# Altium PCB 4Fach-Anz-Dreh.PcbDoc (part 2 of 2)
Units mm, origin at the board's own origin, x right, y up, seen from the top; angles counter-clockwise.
Board outline 160 x 100 mm, 2 copper layers (Top Layer, Bottom Layer), stack 1.601 mm thick; 204 components, 197 nets, 945 pads, 254 vias.
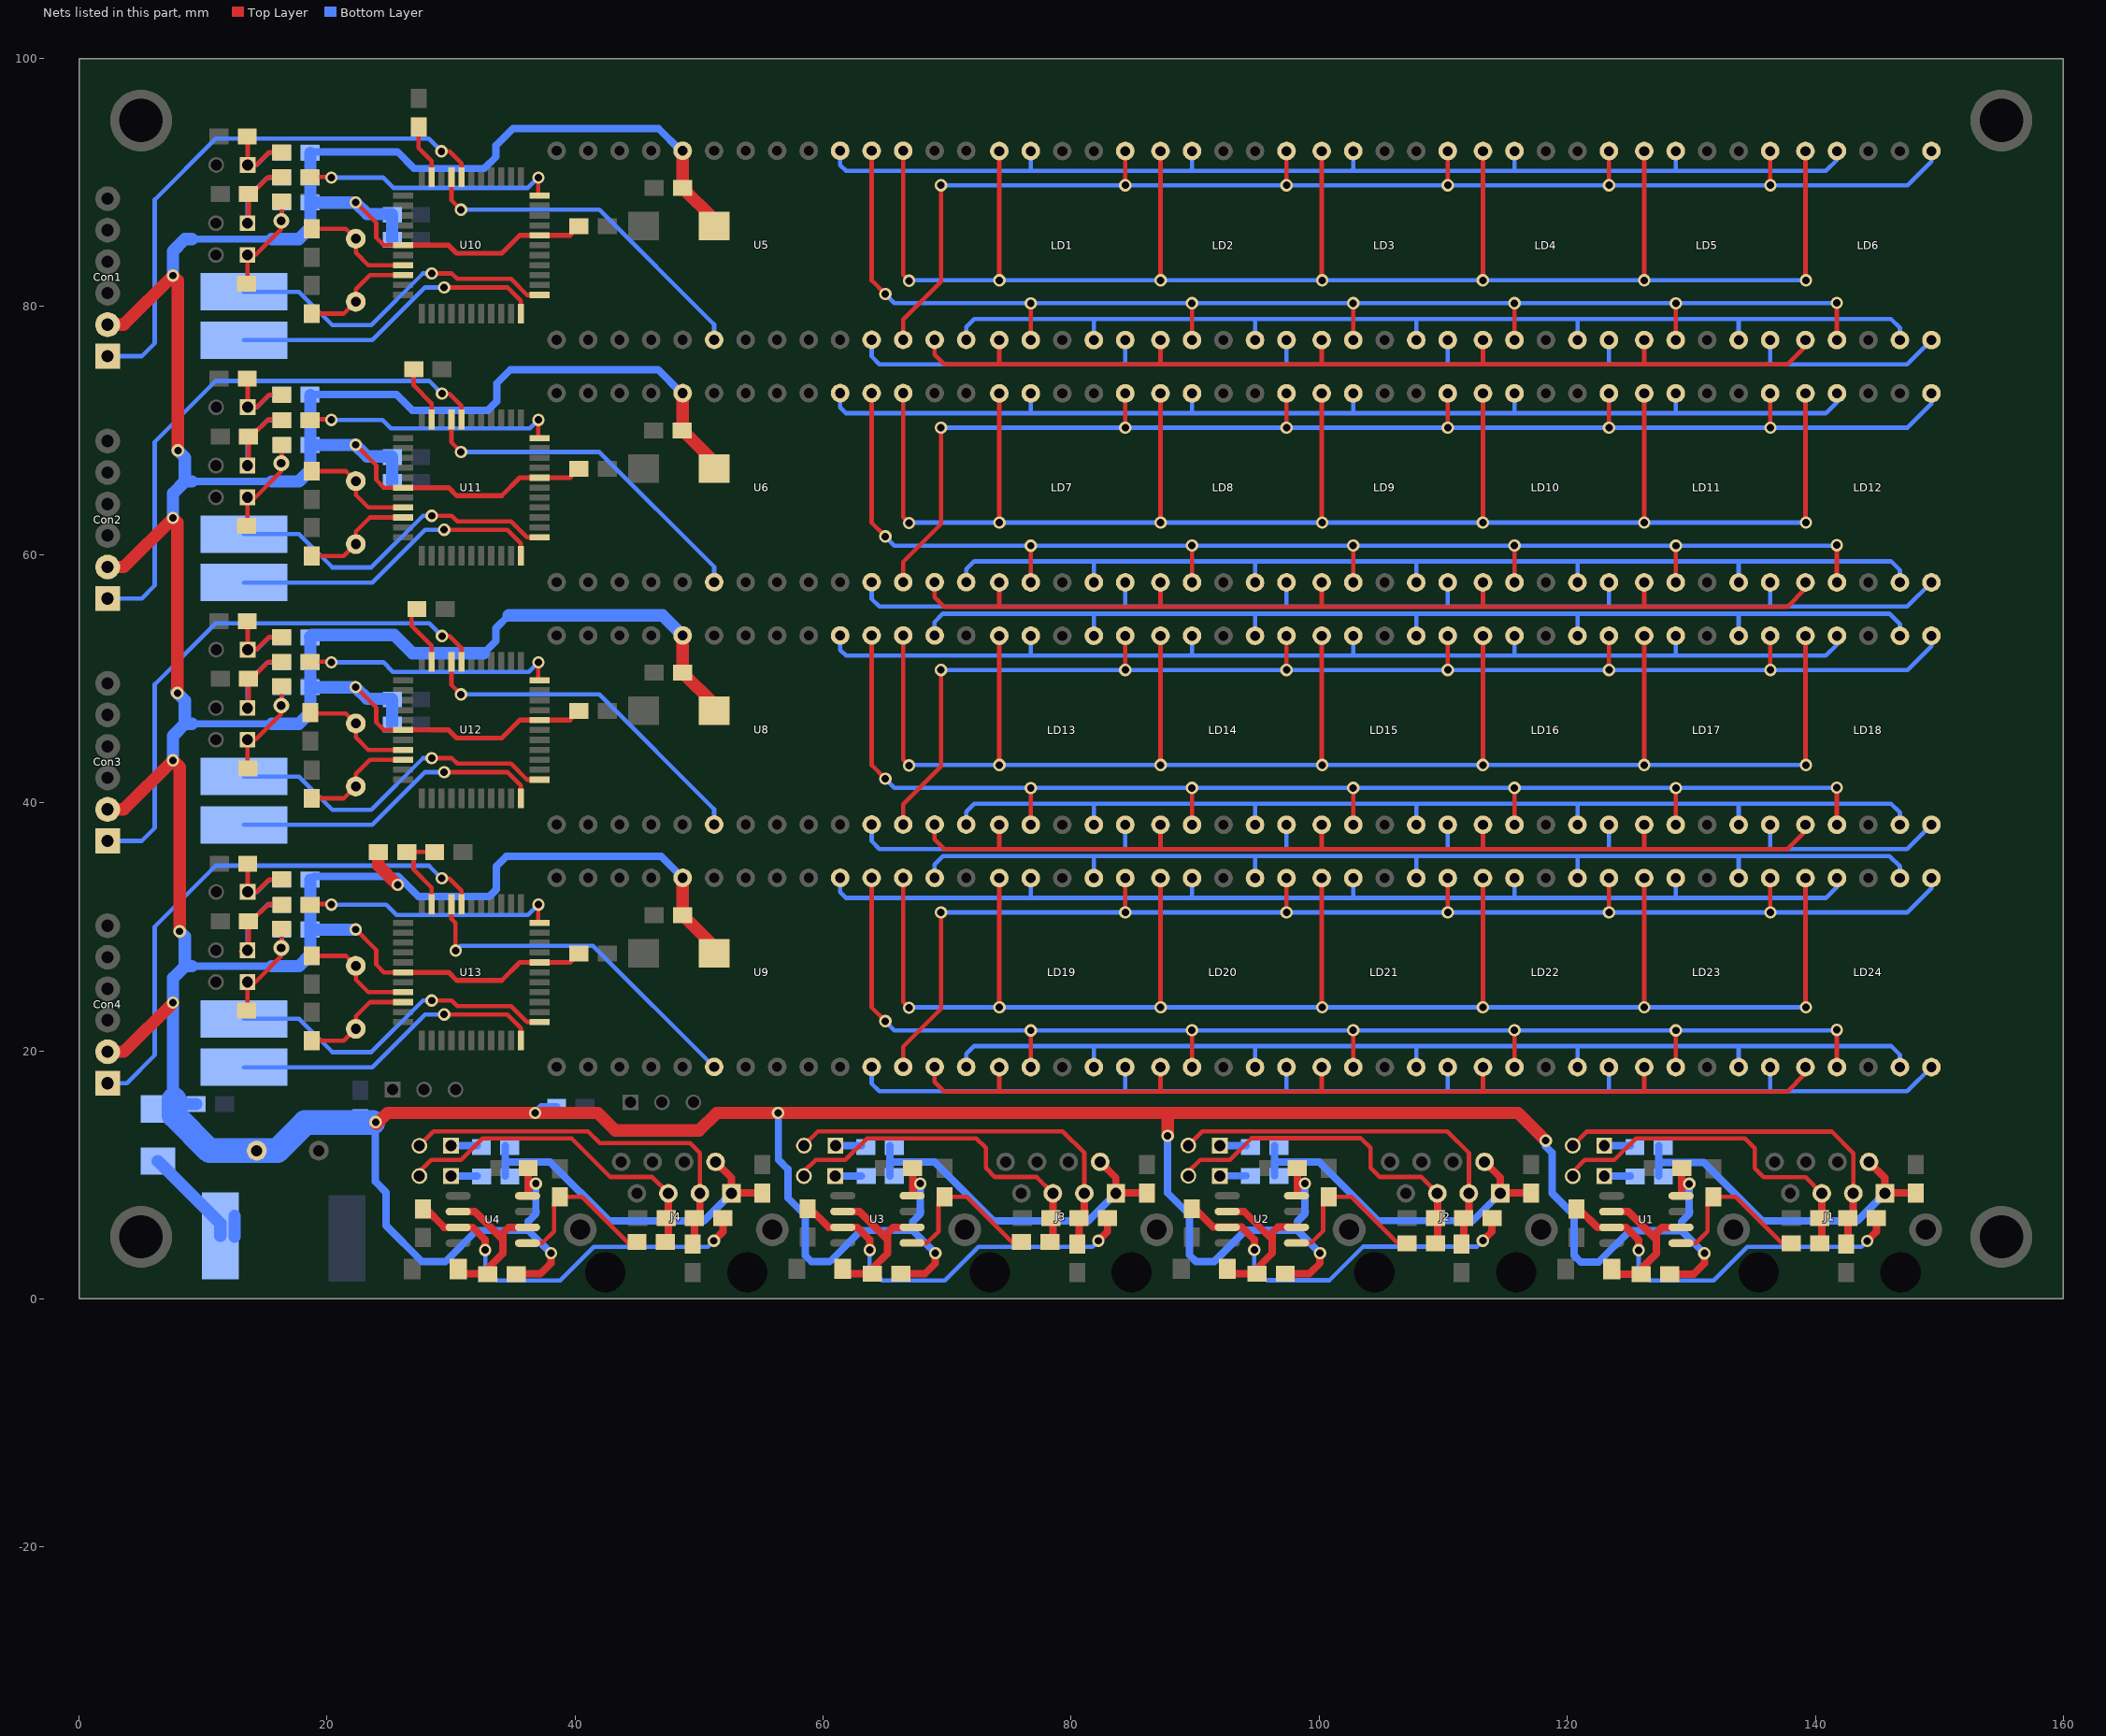
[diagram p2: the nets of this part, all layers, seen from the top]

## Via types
v1: diameter 1, hole 0.6, Top Layer to Bottom Layer, 249 vias
v2: diameter 1.27, hole 0.711, Top Layer to Bottom Layer, 5 vias

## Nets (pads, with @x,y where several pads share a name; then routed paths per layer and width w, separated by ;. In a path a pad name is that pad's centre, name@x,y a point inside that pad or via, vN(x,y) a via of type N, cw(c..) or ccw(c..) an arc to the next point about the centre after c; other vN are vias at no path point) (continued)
LED-A-3: LD13.7 LD14.7 LD15.7 LD16.7 LD17.7 LD18.7 U8.27 | length 89.4
  Bottom Layer w0.35: U8.27@68.99,53.48 68.99,54.56 69.67,55.24 81.82,55.24 ; LD13.7@81.82,53.46 81.82,55.24 ; LD14.7@94.82,53.46 94.82,55.24 ; LD15.7@107.82,53.46 107.82,55.24 ; LD16.7@120.82,53.46 120.82,55.24 ; LD17.7@133.82,53.46 133.82,55.24 ; LD18.7@146.82,53.46 146.82,54.4 145.98,55.24 133.82,55.24 ; 81.82,55.24 94.82,55.24 ; 94.82,55.24 107.82,55.24 ; 107.82,55.24 120.82,55.24 ; 120.82,55.24 133.82,55.24
LED-A-4: LD19.7 LD20.7 LD21.7 LD22.7 LD23.7 LD24.7 U9.27 | length 89.4
  Bottom Layer w0.35: U9.27@68.99,33.94 68.99,35.02 69.67,35.7 81.82,35.7 ; LD19.7@81.82,33.92 81.82,35.7 ; LD20.7@94.82,33.92 94.82,35.7 ; LD21.7@107.82,33.92 107.82,35.7 ; LD22.7@120.82,33.92 120.82,35.7 ; LD23.7@133.82,33.92 133.82,35.7 ; LD24.7@146.82,33.92 146.82,34.86 145.98,35.7 133.82,35.7 ; 81.82,35.7 94.82,35.7 ; 94.82,35.7 107.82,35.7 ; 107.82,35.7 120.82,35.7 ; 120.82,35.7 133.82,35.7
LED-B-1: LD1.6 LD2.6 LD3.6 LD4.6 LD5.6 LD6.6 U5.3 | length 109
  Top Layer w0.35: U5.3@66.45,77.32 66.45,78.96 69.5,82.01 v1(69.5,89.78) ; v1(84.36,89.78) LD1.6@84.36,92.54 ; v1(97.36,89.78) LD2.6@97.36,92.54 ; v1(110.36,89.78) LD3.6@110.36,92.54 ; v1(123.36,89.78) LD4.6@123.36,92.54 ; LD5.6@136.36,92.54 136.36,89.79 v1(136.37,89.78)
  Bottom Layer w0.35: v1(69.5,89.78) v1(84.36,89.78) ; LD6.6@149.36,92.54 149.36,91.7 147.44,89.78 v1(136.37,89.78) v1@123.37,89.78 ; v1(84.36,89.78) v1@84.37,89.78 ; v1(84.36,89.78) v1@84.37,89.78 ; v1@84.37,89.78 v1(97.36,89.78) v1(110.36,89.78) v1(123.36,89.78) ; v1(123.36,89.78) v1@123.37,89.78 ; v1(123.36,89.78) v1@123.37,89.78
LED-B-2: LD7.6 LD8.6 LD9.6 LD10.6 LD11.6 LD12.6 U6.3 | length 109
  Top Layer w0.35: U6.3@66.45,57.78 66.45,59.42 69.5,62.47 v1(69.5,70.24) ; v1(84.36,70.24) LD7.6@84.36,73 ; v1(97.36,70.24) LD8.6@97.36,73 ; v1(110.36,70.24) LD9.6@110.36,73 ; v1(123.36,70.24) LD10.6@123.36,73 ; LD11.6@136.36,73 136.36,70.25 v1(136.37,70.24)
  Bottom Layer w0.35: v1(69.5,70.24) v1(84.36,70.24) ; v2(149.36,73) 149.36,72.16 147.44,70.24 v1(136.37,70.24) v1@123.37,70.24 ; v1(84.36,70.24) v1@84.37,70.24 ; v1(84.36,70.24) v1@84.37,70.24 ; v1@84.37,70.24 v1(97.36,70.24) v1(110.36,70.24) v1(123.36,70.24) ; v1(123.36,70.24) v1@123.37,70.24 ; v1(123.36,70.24) v1@123.37,70.24
LED-B-3: LD13.6 LD14.6 LD15.6 LD16.6 LD17.6 LD18.6 U8.3 | length 109
  Top Layer w0.35: U8.3@66.45,38.24 66.45,39.88 69.5,42.93 v1(69.5,50.7) ; v1(84.36,50.7) LD13.6@84.36,53.46 ; v1(97.36,50.7) LD14.6@97.36,53.46 ; v1(110.36,50.7) LD15.6@110.36,53.46 ; v1(123.36,50.7) LD16.6@123.36,53.46 ; LD17.6@136.36,53.46 136.36,50.71 v1(136.37,50.7)
  Bottom Layer w0.35: v1(69.5,50.7) v1(84.36,50.7) ; LD18.6@149.36,53.46 149.36,52.62 147.44,50.7 v1(136.37,50.7) v1@123.37,50.7 ; v1(84.36,50.7) v1@84.37,50.7 ; v1(84.36,50.7) v1@84.37,50.7 ; v1@84.37,50.7 v1(97.36,50.7) v1(110.36,50.7) v1(123.36,50.7) ; v1(123.36,50.7) v1@123.37,50.7 ; v1(123.36,50.7) v1@123.37,50.7
LED-B-4: LD19.6 LD20.6 LD21.6 LD22.6 LD23.6 LD24.6 U9.3 | length 109
  Top Layer w0.35: U9.3@66.45,18.7 66.45,20.34 69.5,23.39 v1(69.5,31.16) ; v1(84.36,31.16) LD19.6@84.36,33.92 ; v1(97.36,31.16) LD20.6@97.36,33.92 ; v1(110.36,31.16) LD21.6@110.36,33.92 ; v1(123.36,31.16) LD22.6@123.36,33.92 ; LD23.6@136.36,33.92 136.36,31.17 v1(136.37,31.16)
  Bottom Layer w0.35: v1(69.5,31.16) v1(84.36,31.16) ; LD24.6@149.36,33.92 149.36,33.08 147.44,31.16 v1(136.37,31.16) v1@123.37,31.16 ; v1(84.36,31.16) v1@84.37,31.16 ; v1(84.36,31.16) v1@84.37,31.16 ; v1@84.37,31.16 v1(97.36,31.16) v1(110.36,31.16) v1(123.36,31.16) ; v1(123.36,31.16) v1@123.37,31.16 ; v1(123.36,31.16) v1@123.37,31.16
LED-C-1: LD1.4 LD2.4 LD3.4 LD4.4 LD5.4 LD6.4 U5.1 | length 86.3
  Bottom Layer w0.35: U5.1@71.53,77.32 71.53,78.36 72.17,79 81.8,79 ; LD1.4@81.82,77.3 81.82,78.98 81.8,79 ; LD2.4@94.82,77.3 94.82,78.95 94.87,79 ; LD3.4@107.82,77.3 107.82,78.97 107.85,79 ; LD4.4@120.82,77.3 120.82,78.98 ; LD5.4@133.82,77.3 133.82,78.9 ; LD6.4@146.82,77.3 146.82,78.28 146.1,79 107.85,79 ; 81.8,79 94.87,79 ; 94.87,79 107.85,79
LED-C-2: LD7.4 LD8.4 LD9.4 LD10.4 LD11.4 LD12.4 U6.1 | length 86.3
  Bottom Layer w0.35: U6.1@71.53,57.78 71.53,58.82 72.17,59.46 81.8,59.46 ; LD7.4@81.82,57.76 81.82,59.44 81.8,59.46 ; LD8.4@94.82,57.76 94.82,59.41 94.87,59.46 ; LD9.4@107.82,57.76 107.82,59.43 107.85,59.46 ; LD10.4@120.82,57.76 120.82,59.44 ; LD11.4@133.82,57.76 133.82,59.36 ; LD12.4@146.82,57.76 146.82,58.74 146.1,59.46 107.85,59.46 ; 81.8,59.46 94.87,59.46 ; 94.87,59.46 107.85,59.46
LED-C-3: LD13.4 LD14.4 LD15.4 LD16.4 LD17.4 LD18.4 U8.1 | length 86.3
  Bottom Layer w0.35: U8.1@71.53,38.24 71.53,39.28 72.17,39.92 81.8,39.92 ; LD13.4@81.82,38.22 81.82,39.9 81.8,39.92 ; LD14.4@94.82,38.22 94.82,39.87 94.87,39.92 ; LD15.4@107.82,38.22 107.82,39.89 107.85,39.92 ; LD16.4@120.82,38.22 120.82,39.9 ; LD17.4@133.82,38.22 133.82,39.82 ; LD18.4@146.82,38.22 146.82,39.2 146.1,39.92 107.85,39.92 ; 81.8,39.92 94.87,39.92 ; 94.87,39.92 107.85,39.92
LED-C-4: LD19.4 LD20.4 LD21.4 LD22.4 LD23.4 LD24.4 U9.1 | length 86.3
  Bottom Layer w0.35: U9.1@71.53,18.7 71.53,19.74 72.17,20.38 81.8,20.38 ; LD19.4@81.82,18.68 81.82,20.36 81.8,20.38 ; LD20.4@94.82,18.68 94.82,20.33 94.87,20.38 ; LD21.4@107.82,18.68 107.82,20.35 107.85,20.38 ; LD22.4@120.82,18.68 120.82,20.36 ; LD23.4@133.82,18.68 133.82,20.28 ; LD24.4@146.82,18.68 146.82,19.66 146.1,20.38 107.85,20.38 ; 81.8,20.38 94.87,20.38 ; 94.87,20.38 107.85,20.38
LED-D-1: LD1.2 LD2.2 LD3.2 LD4.2 LD5.2 LD6.2 U5.25 | length 106.9
  Top Layer w0.35: U5.25@63.91,92.56 63.91,82.11 v1(65.01,81.01) ; LD1.2@76.74,77.3 v1(76.74,80.26) ; LD2.2@89.74,77.3 v1(89.74,80.27) ; LD3.2@102.74,77.3 v1(102.74,80.27) ; LD4.2@115.74,77.3 v1(115.74,80.27) ; LD5.2@128.74,77.3 128.74,80.25 v1(128.75,80.26) ; v1(141.73,80.3) 141.73,77.31 LD6.2@141.74,77.3
  Bottom Layer w0.35: v1(65.01,81.01) 65.75,80.27 v1@76.74,80.27 ; v1(76.74,80.26) v1@76.74,80.27 ; v1(128.75,80.26) v1@128.75,80.27 ; v1(141.73,80.3) 141.7,80.27 v1@128.75,80.27 ; v1@76.74,80.27 v1(89.74,80.27) v1(102.74,80.27) v1(115.74,80.27) v1@128.75,80.27
LED-D-2: LD7.2 LD8.2 LD9.2 LD10.2 LD11.2 LD12.2 U6.25 | length 106.9
  Top Layer w0.35: U6.25@63.91,73.02 63.91,62.57 v1(65.01,61.47) ; LD7.2@76.74,57.76 v1(76.74,60.72) ; LD8.2@89.74,57.76 v1(89.74,60.73) ; LD9.2@102.74,57.76 v1(102.74,60.73) ; LD10.2@115.74,57.76 v1(115.74,60.73) ; LD11.2@128.74,57.76 128.74,60.71 v1(128.75,60.72) ; v1(141.73,60.76) 141.73,57.77 LD12.2@141.74,57.76
  Bottom Layer w0.35: v1(65.01,61.47) 65.75,60.73 v1@76.74,60.73 ; v1(76.74,60.72) v1@76.74,60.73 ; v1(128.75,60.72) v1@128.75,60.73 ; v1(141.73,60.76) 141.7,60.73 v1@128.75,60.73 ; v1@76.74,60.73 v1(89.74,60.73) v1(102.74,60.73) v1(115.74,60.73) v1@128.75,60.73
LED-D-3: LD13.2 LD14.2 LD15.2 LD16.2 LD17.2 LD18.2 U8.25 | length 106.9
  Top Layer w0.35: U8.25@63.91,53.48 63.91,43.03 v1(65.01,41.93) ; LD13.2@76.74,38.22 v1(76.74,41.18) ; LD14.2@89.74,38.22 v1(89.74,41.19) ; LD15.2@102.74,38.22 v1(102.74,41.19) ; LD16.2@115.74,38.22 v1(115.74,41.19) ; LD17.2@128.74,38.22 128.74,41.17 v1(128.75,41.18) ; v1(141.73,41.22) 141.73,38.23 LD18.2@141.74,38.22
  Bottom Layer w0.35: v1(65.01,41.93) 65.75,41.19 v1@76.74,41.19 ; v1(76.74,41.18) v1@76.74,41.19 ; v1(128.75,41.18) v1@128.75,41.19 ; v1(141.73,41.22) 141.7,41.19 v1@128.75,41.19 ; v1@76.74,41.19 v1(89.74,41.19) v1(102.74,41.19) v1(115.74,41.19) v1@128.75,41.19
LED-D-4: LD19.2 LD20.2 LD21.2 LD22.2 LD23.2 LD24.2 U9.25 | length 106.9
  Top Layer w0.35: U9.25@63.91,33.94 63.91,23.49 v1(65.01,22.39) ; LD19.2@76.74,18.68 v1(76.74,21.64) ; LD20.2@89.74,18.68 v1(89.74,21.65) ; LD21.2@102.74,18.68 v1(102.74,21.65) ; LD22.2@115.74,18.68 v1(115.74,21.65) ; LD23.2@128.74,18.68 128.74,21.63 v1(128.75,21.64) ; v1(141.73,21.68) 141.73,18.69 LD24.2@141.74,18.68
  Bottom Layer w0.35: v1(65.01,22.39) 65.75,21.65 v1@76.74,21.65 ; v1(76.74,21.64) v1@76.74,21.65 ; v1(128.75,21.64) v1@128.75,21.65 ; v1(141.73,21.68) 141.7,21.65 v1@128.75,21.65 ; v1@76.74,21.65 v1(89.74,21.65) v1(102.74,21.65) v1(115.74,21.65) v1@128.75,21.65
LED-DP-1: LD1.5 LD2.5 LD3.5 LD4.5 LD5.5 LD6.5 U5.4 | length 97.6
  Bottom Layer w0.35: U5.4@63.91,77.32 63.91,75.97 64.53,75.35 84.38,75.35 ; LD1.5@84.36,77.3 84.36,75.37 84.38,75.35 ; LD2.5@97.36,77.3 97.36,75.37 97.38,75.35 ; 110.36,75.4 LD3.5@110.36,77.3 ; LD4.5@123.36,77.3 123.36,75.35 ; LD5.5@136.36,77.3 136.36,75.42 136.43,75.35 ; LD6.5@149.36,77.3 147.41,75.35 136.43,75.35 ; 84.38,75.35 97.38,75.35 ; 97.38,75.35 123.36,75.35 ; 123.36,75.35 136.43,75.35
LED-DP-2: LD7.5 LD8.5 LD9.5 LD10.5 LD11.5 LD12.5 U6.4 | length 97.6
  Bottom Layer w0.35: U6.4@63.91,57.78 63.91,56.43 64.53,55.81 84.38,55.81 ; LD7.5@84.36,57.76 84.36,55.83 84.38,55.81 ; LD8.5@97.36,57.76 97.36,55.83 97.38,55.81 ; 110.36,55.86 LD9.5@110.36,57.76 ; LD10.5@123.36,57.76 123.36,55.81 ; LD11.5@136.36,57.76 136.36,55.88 136.43,55.81 ; LD12.5@149.36,57.76 147.41,55.81 136.43,55.81 ; 84.38,55.81 97.38,55.81 ; 97.38,55.81 123.36,55.81 ; 123.36,55.81 136.43,55.81
LED-DP-3: LD13.5 LD14.5 LD15.5 LD16.5 LD17.5 LD18.5 U8.4 | length 97.6
  Bottom Layer w0.35: U8.4@63.91,38.24 63.91,36.89 64.53,36.27 84.38,36.27 ; LD13.5@84.36,38.22 84.36,36.29 84.38,36.27 ; LD14.5@97.36,38.22 97.36,36.29 97.38,36.27 ; 110.36,36.32 LD15.5@110.36,38.22 ; LD16.5@123.36,38.22 123.36,36.27 ; LD17.5@136.36,38.22 136.36,36.34 136.43,36.27 ; LD18.5@149.36,38.22 147.41,36.27 136.43,36.27 ; 84.38,36.27 97.38,36.27 ; 97.38,36.27 123.36,36.27 ; 123.36,36.27 136.43,36.27
LED-DP-4: LD19.5 LD20.5 LD21.5 LD22.5 LD23.5 LD24.5 U9.4 | length 97.6
  Bottom Layer w0.35: U9.4@63.91,18.7 63.91,17.35 64.53,16.73 84.38,16.73 ; LD19.5@84.36,18.68 84.36,16.75 84.38,16.73 ; LD20.5@97.36,18.68 97.36,16.75 97.38,16.73 ; 110.36,16.78 LD21.5@110.36,18.68 ; LD22.5@123.36,18.68 123.36,16.73 ; LD23.5@136.36,18.68 136.36,16.8 136.43,16.73 ; LD24.5@149.36,18.68 147.41,16.73 136.43,16.73 ; 84.38,16.73 97.38,16.73 ; 97.38,16.73 123.36,16.73 ; 123.36,16.73 136.43,16.73
LED-E-1: LD1.1 LD2.1 LD3.1 LD4.1 LD5.1 LD6.1 U5.2 | length 82.6
  Top Layer w0.35: U5.2@68.99,77.32 68.99,76.12 69.78,75.33 100.19,75.33 ; 74.2,75.41 LD1.1@74.2,77.3 ; 87.2,75.39 LD2.1@87.2,77.3 ; LD3.1@100.2,77.3 100.2,75.34 100.19,75.33 ; LD4.1@113.2,77.3 113.2,75.34 113.19,75.33 ; LD5.1@126.2,77.3 126.2,75.34 126.19,75.33 ; LD6.1@139.2,77.3 139.2,76.78 137.75,75.33 126.19,75.33 ; 100.19,75.33 113.19,75.33 ; 113.19,75.33 126.19,75.33
LED-E-2: LD7.1 LD8.1 LD9.1 LD10.1 LD11.1 LD12.1 U6.2 | length 82.6
  Top Layer w0.35: U6.2@68.99,57.78 68.99,56.58 69.78,55.79 100.19,55.79 ; 74.2,55.87 LD7.1@74.2,57.76 ; 87.2,55.85 LD8.1@87.2,57.76 ; LD9.1@100.2,57.76 100.2,55.8 100.19,55.79 ; LD10.1@113.2,57.76 113.2,55.8 113.19,55.79 ; LD11.1@126.2,57.76 126.2,55.8 126.19,55.79 ; LD12.1@139.2,57.76 139.2,57.24 137.75,55.79 126.19,55.79 ; 100.19,55.79 113.19,55.79 ; 113.19,55.79 126.19,55.79
LED-E-3: LD13.1 LD14.1 LD15.1 LD16.1 LD17.1 LD18.1 U8.2 | length 82.6
  Top Layer w0.35: U8.2@68.99,38.24 68.99,37.04 69.78,36.25 100.19,36.25 ; 74.2,36.33 LD13.1@74.2,38.22 ; 87.2,36.31 LD14.1@87.2,38.22 ; LD15.1@100.2,38.22 100.2,36.26 100.19,36.25 ; LD16.1@113.2,38.22 113.2,36.26 113.19,36.25 ; LD17.1@126.2,38.22 126.2,36.26 126.19,36.25 ; LD18.1@139.2,38.22 139.2,37.7 137.75,36.25 126.19,36.25 ; 100.19,36.25 113.19,36.25 ; 113.19,36.25 126.19,36.25
LED-E-4: LD19.1 LD20.1 LD21.1 LD22.1 LD23.1 LD24.1 U9.2 | length 82.6
  Top Layer w0.35: U9.2@68.99,18.7 68.99,17.5 69.78,16.71 100.19,16.71 ; 74.2,16.79 LD19.1@74.2,18.68 ; 87.2,16.77 LD20.1@87.2,18.68 ; LD21.1@100.2,18.68 100.2,16.72 100.19,16.71 ; LD22.1@113.2,18.68 113.2,16.72 113.19,16.71 ; LD23.1@126.2,18.68 126.2,16.72 126.19,16.71 ; LD24.1@139.2,18.68 139.2,18.16 137.75,16.71 126.19,16.71 ; 100.19,16.71 113.19,16.71 ; 113.19,16.71 126.19,16.71
LED-F-1: LD1.9 LD2.9 LD3.9 LD4.9 LD5.9 LD6.9 U5.24 | length 91.3
  Bottom Layer w0.35: U5.24@61.37,92.56 61.37,91.41 61.84,90.94 76.86,90.94 ; LD1.9@76.74,92.54 76.74,91.06 76.86,90.94 ; LD2.9@89.74,92.54 89.74,91.11 89.57,90.94 ; LD3.9@102.74,92.54 102.74,91.09 102.59,90.94 ; LD4.9@115.74,92.54 115.74,90.95 115.75,90.94 ; LD5.9@128.74,92.54 128.74,91.04 128.64,90.94 ; LD6.9@141.49,92.5 141.53,92.54 LD6.9@141.74,92.54 141.74,91.83 140.85,90.94 128.64,90.94 ; 76.86,90.94 89.57,90.94 ; 89.57,90.94 102.59,90.94 ; 102.59,90.94 115.75,90.94 ; 115.75,90.94 128.64,90.94
LED-F-2: LD7.9 LD8.9 LD9.9 LD10.9 LD11.9 LD12.9 U6.24 | length 91.3
  Bottom Layer w0.35: U6.24@61.37,73.02 61.37,71.87 61.84,71.4 76.86,71.4 ; LD7.9@76.74,73 76.74,71.52 76.86,71.4 ; LD8.9@89.74,73 89.74,71.57 89.57,71.4 ; LD9.9@102.74,73 102.74,71.55 102.59,71.4 ; LD10.9@115.74,73 115.74,71.41 115.75,71.4 ; LD11.9@128.74,73 128.74,71.5 128.64,71.4 ; LD12.9@141.49,72.96 141.53,73 LD12.9@141.74,73 141.74,72.29 140.85,71.4 128.64,71.4 ; 76.86,71.4 89.57,71.4 ; 89.57,71.4 102.59,71.4 ; 102.59,71.4 115.75,71.4 ; 115.75,71.4 128.64,71.4
LED-F-3: LD13.9 LD14.9 LD15.9 LD16.9 LD17.9 LD18.9 U8.24 | length 91.3
  Bottom Layer w0.35: U8.24@61.37,53.48 61.37,52.33 61.84,51.86 76.86,51.86 ; LD13.9@76.74,53.46 76.74,51.98 76.86,51.86 ; LD14.9@89.74,53.46 89.74,52.03 89.57,51.86 ; LD15.9@102.74,53.46 102.74,52.01 102.59,51.86 ; LD16.9@115.74,53.46 115.74,51.87 115.75,51.86 ; LD17.9@128.74,53.46 128.74,51.96 128.64,51.86 ; LD18.9@141.49,53.42 141.53,53.46 LD18.9@141.74,53.46 141.74,52.75 140.85,51.86 128.64,51.86 ; 76.86,51.86 89.57,51.86 ; 89.57,51.86 102.59,51.86 ; 102.59,51.86 115.75,51.86 ; 115.75,51.86 128.64,51.86
LED-F-4: LD19.9 LD20.9 LD21.9 LD22.9 LD23.9 LD24.9 U9.24 | length 91.3
  Bottom Layer w0.35: U9.24@61.37,33.94 61.37,32.79 61.84,32.32 76.86,32.32 ; LD19.9@76.74,33.92 76.74,32.44 76.86,32.32 ; LD20.9@89.74,33.92 89.74,32.49 89.57,32.32 ; LD21.9@102.74,33.92 102.74,32.47 102.59,32.32 ; LD22.9@115.74,33.92 115.74,32.33 115.75,32.32 ; LD23.9@128.74,33.92 128.74,32.42 128.64,32.32 ; LD24.9@141.49,33.88 141.53,33.92 LD24.9@141.74,33.92 141.74,33.21 140.85,32.32 128.64,32.32 ; 76.86,32.32 89.57,32.32 ; 89.57,32.32 102.59,32.32 ; 102.59,32.32 115.75,32.32 ; 115.75,32.32 128.64,32.32
LED-G-1: LD1.10 LD2.10 LD3.10 LD4.10 LD5.10 LD6.10 U5.26 | length 145.6
  Top Layer w0.35: U5.26@66.45,92.56 66.45,82.56 v1(66.93,82.08) ; LD1.10@74.2,92.54 74.2,82.12 v1(74.21,82.12) ; LD2.10@87.2,92.54 87.2,82.12 v1(87.21,82.12) ; LD3.10@100.2,92.54 100.2,82.12 v1(100.23,82.12) ; v1(113.19,82.12) 113.2,82.12 LD4.10@113.2,92.54 ; LD5.10@126.2,92.54 126.2,82.12 v1(126.21,82.12) ; LD6.10@139.2,92.54 139.2,82.12 v1(139.24,82.12)
  Bottom Layer w0.35: v1@66.93,82.12 v1(100.23,82.12) v1(113.19,82.12) v1(139.24,82.12)
LED-G-2: LD7.10 LD8.10 LD9.10 LD10.10 LD11.10 LD12.10 U6.26 | length 145.6
  Top Layer w0.35: U6.26@66.45,73.02 66.45,63.02 v1(66.93,62.54) ; LD7.10@74.2,73 74.2,62.58 v1(74.21,62.58) ; LD8.10@87.2,73 87.2,62.58 v1(87.21,62.58) ; LD9.10@100.2,73 100.2,62.58 v1(100.23,62.58) ; v1(113.19,62.58) 113.2,62.58 LD10.10@113.2,73 ; LD11.10@126.2,73 126.2,62.58 v1(126.21,62.58) ; LD12.10@139.2,73 139.2,62.58 v1(139.24,62.58)
  Bottom Layer w0.35: v1@66.93,62.58 v1(100.23,62.58) v1(113.19,62.58) v1(139.24,62.58)
LED-G-3: LD13.10 LD14.10 LD15.10 LD16.10 LD17.10 LD18.10 U8.26 | length 145.6
  Top Layer w0.35: U8.26@66.45,53.48 66.45,43.48 v1(66.93,43) ; LD13.10@74.2,53.46 74.2,43.04 v1(74.21,43.04) ; LD14.10@87.2,53.46 87.2,43.04 v1(87.21,43.04) ; LD15.10@100.2,53.46 100.2,43.04 v1(100.23,43.04) ; v1(113.19,43.04) 113.2,43.04 LD16.10@113.2,53.46 ; LD17.10@126.2,53.46 126.2,43.04 v1(126.21,43.04) ; LD18.10@139.2,53.46 139.2,43.04 v1(139.24,43.04)
  Bottom Layer w0.35: v1@66.93,43.04 v1(100.23,43.04) v1(113.19,43.04) v1(139.24,43.04)
LED-G-4: LD19.10 LD20.10 LD21.10 LD22.10 LD23.10 LD24.10 U9.26 | length 145.6
  Top Layer w0.35: U9.26@66.45,33.94 66.45,23.94 v1(66.93,23.46) ; LD19.10@74.2,33.92 74.2,23.5 v1(74.21,23.5) ; LD20.10@87.2,33.92 87.2,23.5 v1(87.21,23.5) ; LD21.10@100.2,33.92 100.2,23.5 v1(100.23,23.5) ; v1(113.19,23.5) 113.2,23.5 LD22.10@113.2,33.92 ; LD23.10@126.2,33.92 126.2,23.5 v1(126.21,23.5) ; LD24.10@139.2,33.92 139.2,23.5 v1(139.24,23.5)
  Bottom Layer w0.35: v1@66.93,23.5 v1(100.23,23.5) v1(113.19,23.5) v1(139.24,23.5)
MCLR/VPP-1: Con1.1 U10.18 | length 43.9
  Top Layer w0.35: 29.85,92.52 30.83,91.54 U10.18@30.83,90.44
  Bottom Layer w0.35: Con1.1@2.3,76 5.05,76 6.1,77.05 6.1,88.62 11.025,93.545 26.53,93.545 28.195,93.545 v1(29.22,92.52)
MCLR/VPP-2: Con2.1 U11.18 | length 44.5
  Top Layer w0.35: v1(29.26,72.98) 29.85,72.98 30.319,72.511 30.83,72 U11.18@30.83,70.9
  Bottom Layer w0.35: Con2.1@2.3,56.46 5.05,56.46 6.1,57.51 6.1,69.08 11.025,74.005 28.235,74.005 v1(29.26,72.98)
MCLR/VPP-3: Con3.1 U12.18 | length 44.5
  Top Layer w0.35: v1(29.26,53.44) 29.85,53.44 30.83,52.46 U12.18@30.83,51.36
  Bottom Layer w0.35: Con3.1@2.3,36.92 5.05,36.92 6.1,37.97 6.1,49.54 11.025,54.465 27.365,54.465 28.235,54.465 v1(29.26,53.44)
MCLR/VPP-4: Con4.1 U13.18 | length 43.9
  Top Layer w0.35: v1(29.25,33.9) 29.85,33.9 30.83,32.92 U13.18@30.83,31.82
  Bottom Layer w0.35: Con4.1@2.38,17.49 2.3,17.41 Con4.1@2.3,17.38 3.85,17.38 6.1,19.63 6.1,30 11.025,34.925 26.98,34.925 27.365,34.925 28.215,34.925 v1@29.24,33.9
MODE-1: U5.9 U10.19 | length 28.4
  Top Layer w0.35: U10.19@30.03,90.44 30.03,88.58 v1(30.8,87.81)
  Bottom Layer w0.35: v1(30.8,87.81) 41.96,87.81 51.21,78.56 U5.9@51.21,77.32
MODE-2: U6.9 U11.19 | length 28.4
  Top Layer w0.35: U11.19@30.03,70.9 30.03,69.04 v1(30.8,68.27)
  Bottom Layer w0.35: v1(30.8,68.27) 41.96,68.27 51.21,59.02 U6.9@51.21,57.78
MODE-3: U8.9 U12.19 | length 28.4
  Top Layer w0.35: U12.19@30.03,51.36 30.03,49.5 v1(30.8,48.73)
  Bottom Layer w0.35: v1(30.8,48.73) 41.96,48.73 51.21,39.48 U8.9@51.21,38.24
MODE-4: U9.9 U13.19 | length 28.9
  Top Layer w0.35: U13.19@30.03,31.82 30.03,30.63 30.36,30.3 v1(30.36,28.08)
  Bottom Layer w0.35: v1(30.36,28.08) 30.75,28.47 41.44,28.47 U9.9@51.21,18.7
NetC13_1: C13.1 U10.31 XT1.1 | length 9.3
  Top Layer w0.35: C13.1@18.76,79.43 21.35,79.43 XT1.1@22.31,80.39 22.31,81.41 23.44,82.54 U10.31@26.13,82.54
NetC14_1: C14.1 R1.2 R6.1 T1.1 | length 9.7
  Top Layer w0.35: C14.1@13.52,81.85 13.58,81.91 T1.1@13.58,84.16 ; T1.1@13.52,84.1 T1.1@13.58,84.16 ; v2(16.3,86.91) 16.3,86.24 14.22,84.16 T1.1@13.58,84.16 ; R6.1@16.32,88.46 16.32,86.99 v2@16.35,86.96
  Bottom Layer w0.35: v2(16.3,86.91) 16.35,86.96 R1.2@16.35,88.38
NetC17_1: C17.1 U10.30 XT1.2 | length 9.2
  Top Layer w0.35: C17.1@18.76,86.27 21.51,86.27 XT1.2@22.31,85.47 22.31,84.35 23.32,83.34 U10.30@26.13,83.34
NetC18_1: C18.1 R9.1 U1.3 | length 30.6
  Top Layer w0.6: C18.1@120.74,7.25 120.95,7.25 122.44,5.76 U1.3@123.58,5.76 124.74,5.76 125.75,4.75 v1(125.75,3.92) ; v1(144.18,4.67) 144.92,5.41 R9.1@144.92,6.51
  Bottom Layer w0.35: v1(125.75,3.92) 125.75,2.48 126.755,1.475 131.805,1.475 134.52,4.19 143.7,4.19 v1(144.18,4.67)
NetC19_1: C19.1 R7.2 R8.1 T4.1 | length 11.1
  Top Layer w0.35: T4.1@13.58,86.72 13.67,86.81 C19.1@13.67,89.07 13.89,89.07 15.27,90.45 R8.1@16.32,90.45
  Bottom Layer w0.35: T4.1@13.58,86.72 13.58,88.81 15.15,90.38 R7.2@16.35,90.38
NetC20_1: C20.1 R10.2 U1.5 | length 13.3
  Top Layer w0.35: U1.5@129.168,4.49 U1.5@129.22,4.49 ; U1.5@129.22,4.5 130.36,4.5 131.3,5.44 131.3,7.74 C20.1@131.77,8.21 133.57,8.21 137.3,4.48 R10.2@138.07,4.48
NetC21_1: C21.1 R11.2 R15.1 T5.1 | length 8.6
  Top Layer w0.35: C21.1@13.56,93.72 13.6,93.68 T5.1@13.6,91.42 14.28,91.42 15.3,92.44 R15.1@16.32,92.44
  Bottom Layer w0.35: T5.1@13.6,91.42 14.35,91.42 15.33,92.4 R11.2@16.35,92.4
NetC23_1: C23.1 U11.31 XT2.1 | length 9.3
  Top Layer w0.35: C23.1@18.76,59.89 21.35,59.89 XT2.1@22.31,60.85 22.31,61.87 23.44,63 U11.31@26.13,63
NetC24_1: C24.1 R16.2 R21.1 T6.1 | length 9.6
  Top Layer w0.35: C24.1@13.52,62.31 13.58,62.37 T6.1@13.58,64.62 ; T6.1@13.52,64.56 T6.1@13.58,64.62 ; R21.1@16.35,68.84 16.35,67.42 v2(16.3,67.37) 16.3,66.7 14.22,64.62 T6.1@13.58,64.62
  Bottom Layer w0.35: v2@16.35,67.42 R16.2@16.35,68.84
NetC27_1: C27.1 U11.30 XT2.2 | length 9.2
  Top Layer w0.35: C27.1@18.76,66.73 21.51,66.73 XT2.2@22.31,65.93 22.31,64.81 23.32,63.8 U11.30@26.13,63.8
NetC28_1: C28.1 R24.1 U2.3 | length 30.6
  Top Layer w0.6: C28.1@89.75,7.27 89.96,7.27 91.45,5.78 92.59,5.78 93.75,5.78 94.76,4.77 v1(94.76,3.94) ; v1(113.19,4.69) 113.93,5.43 R24.1@113.93,6.53
  Bottom Layer w0.35: v1(94.76,3.94) 94.76,2.5 95.765,1.495 100.815,1.495 103.53,4.21 112.71,4.21 v1(113.19,4.69)
NetC29_1: C29.1 R22.2 R23.1 T9.1 | length 11.1
  Top Layer w0.35: T9.1@13.58,67.18 13.67,67.27 C29.1@13.67,69.53 13.89,69.53 15.27,70.91 R23.1@16.32,70.91
  Bottom Layer w0.35: T9.1@13.58,67.18 13.58,69.27 15.15,70.84 R22.2@16.35,70.84
NetC30_1: C30.1 R25.2 U2.5 | length 13.3
  Top Layer w0.35: U2.5@98.178,4.51 U2.5@98.23,4.51 ; U2.5@98.23,4.52 99.37,4.52 100.31,5.46 100.31,7.76 100.78,8.23 102.58,8.23 106.31,4.5 R25.2@107.08,4.5
NetC31_1: C31.1 R26.2 R30.1 T10.1 | length 8.6
  Top Layer w0.35: C31.1@13.56,74.18 13.6,74.14 T10.1@13.6,71.88 14.28,71.88 15.3,72.9 R30.1@16.32,72.9
  Bottom Layer w0.35: T10.1@13.6,71.88 14.35,71.88 15.33,72.86 R26.2@16.35,72.86
NetC33_1: C33.1 U12.31 XT3.1 | length 9.3
  Top Layer w0.35: C33.1@18.76,40.35 21.35,40.35 XT3.1@22.31,41.31 22.31,42.33 23.44,43.46 U12.31@26.13,43.46
NetC34_1: C34.1 R31.2 R36.1 T11.1 | length 9.6
  Top Layer w0.35: C34.1@13.52,42.77 13.58,42.83 T11.1@13.58,45.08 ; T11.1@13.52,45.02 T11.1@13.58,45.08 ; R36.1@16.32,49.38 16.32,47.85 v2(16.3,47.83) 16.3,47.16 14.22,45.08 T11.1@13.58,45.08
  Bottom Layer w0.35: v2@16.35,47.88 R31.2@16.35,49.3
NetC37_1: C37.1 U12.30 XT3.2 | length 9.2
  Top Layer w0.35: C37.1@18.76,47.19 21.51,47.19 XT3.2@22.31,46.39 22.31,45.27 23.32,44.26 U12.30@26.13,44.26
NetC38_1: C38.1 R39.1 U3.3 | length 30.6
  Top Layer w0.6: C38.1@58.74,7.26 58.95,7.26 60.44,5.77 U3.3@61.58,5.77 62.74,5.77 63.75,4.76 v1(63.75,3.93) ; v1(82.18,4.68) 82.92,5.42 R39.1@82.92,6.52
  Bottom Layer w0.35: v1(63.75,3.93) 63.75,2.49 64.755,1.485 69.805,1.485 72.52,4.2 81.7,4.2 v1(82.18,4.68)
NetC39_1: C39.1 R37.2 R38.1 T14.1 | length 11.1
  Top Layer w0.35: T14.1@13.58,47.64 13.67,47.73 C39.1@13.67,49.99 13.89,49.99 15.27,51.37 R38.1@16.32,51.37
  Bottom Layer w0.35: T14.1@13.58,47.64 13.58,49.73 15.15,51.3 R37.2@16.35,51.3
NetC40_1: C40.1 R40.2 U3.5 | length 13.3
  Top Layer w0.35: U3.5@67.168,4.5 U3.5@67.22,4.5 ; U3.5@67.22,4.51 68.36,4.51 69.3,5.45 69.3,7.75 C40.1@69.77,8.22 71.57,8.22 75.3,4.49 R40.2@76.07,4.49
NetC41_1: C41.1 R41.2 R45.1 T15.1 | length 8.6
  Top Layer w0.35: C41.1@13.56,54.64 13.6,54.6 T15.1@13.6,52.34 14.28,52.34 15.3,53.36 R45.1@16.32,53.36
  Bottom Layer w0.35: T15.1@13.6,52.34 14.35,52.34 15.33,53.32 R41.2@16.35,53.32
NetC43_1: C43.1 U13.31 XT4.1 | length 9.3
  Top Layer w0.35: C43.1@18.76,20.81 21.35,20.81 XT4.1@22.31,21.77 22.31,22.79 23.44,23.92 U13.31@26.13,23.92
NetC44_1: C44.1 R46.2 R51.1 T16.1 | length 9.6
  Top Layer w0.35: C44.1@13.52,23.23 13.58,23.29 T16.1@13.58,25.54 ; T16.1@13.52,25.48 T16.1@13.58,25.54 ; R51.1@16.32,29.84 16.32,28.31 v2(16.3,28.29) 16.3,27.62 14.22,25.54 T16.1@13.58,25.54
  Bottom Layer w0.35: v2@16.35,28.34 R46.2@16.35,29.76
NetC47_1: C47.1 U13.30 XT4.2 | length 9.2
  Top Layer w0.35: C47.1@18.76,27.65 21.51,27.65 XT4.2@22.31,26.85 22.31,25.73 23.32,24.72 U13.30@26.13,24.72
NetC48_1: C48.1 R54.1 U4.3 | length 30.6
  Top Layer w0.6: C48.1@27.74,7.26 27.95,7.26 29.44,5.77 30.58,5.77 31.74,5.77 32.75,4.76 v1(32.75,3.93) ; v1(51.18,4.68) 51.92,5.42 R54.1@51.92,6.52
  Bottom Layer w0.35: v1(32.75,3.93) 32.75,2.49 33.755,1.485 38.805,1.485 41.52,4.2 50.7,4.2 v1(51.18,4.68)
NetC49_1: C49.1 R52.2 R53.1 T19.1 | length 11.7
  Top Layer w0.35: T19.1@13.07,28.03 13.51,28.03 13.67,28.19 C49.1@13.67,30.45 13.89,30.45 15.27,31.83 R53.1@16.32,31.83
  Bottom Layer w0.35: T19.1@13.58,28.1 13.58,30.19 15.15,31.76 R52.2@16.35,31.76
NetC50_1: C50.1 R55.2 U4.5 | length 13.3
  Top Layer w0.35: U4.5@36.168,4.5 U4.5@36.22,4.5 ; U4.5@36.22,4.51 37.36,4.51 38.3,5.45 38.3,7.75 38.77,8.22 40.57,8.22 44.3,4.49 R55.2@45.07,4.49
NetC51_1: C51.1 R56.2 R60.1 T20.1 | length 8.6
  Top Layer w0.35: C51.1@13.56,35.1 C51.1@13.6,35.06 T20.1@13.6,32.8 14.28,32.8 15.3,33.82 R60.1@16.32,33.82
  Bottom Layer w0.35: T20.1@13.6,32.8 14.35,32.8 15.33,33.78 R56.2@16.35,33.78
NetD1_A: D1.A X1.1 | length 9.8
  Bottom Layer w1: D1.A@6.35,11.11 11.39,6.07 X1.1@11.39,5.07 ; X1.1@12.54,5.02 X1.1@12.54,6.69
NetD5_A: D5.A R2.2 U1.2 U1.6 | length 13.4
  Top Layer w0.6: D5.A@123.58,2.4 123.98,2 R2.2@125.97,2 125.97,2.44 127.18,3.65 127.18,4.77 ; U1.2@123.58,7.03 124.92,7.03 127.18,4.77 ; 126.96,5.08 127.18,5.3 ; U1.6@129.168,5.76 127.64,5.76 127.18,5.3 ; 127.18,4.77 127.18,5.3
NetD6_A: D6.A R17.2 U2.2 U2.6 | length 13.4
  Top Layer w0.6: D6.A@92.59,2.42 92.99,2.02 94.98,2.02 94.98,2.46 96.19,3.67 96.19,4.79 ; U2.2@92.59,7.05 93.93,7.05 96.19,4.79 ; 95.97,5.1 96.19,5.32 ; U2.6@98.178,5.78 96.65,5.78 96.19,5.32 ; 96.19,4.79 96.19,5.32
NetD7_A: D7.A R32.2 U3.2 U3.6 | length 13.4
  Top Layer w0.6: D7.A@61.58,2.41 61.98,2.01 R32.2@63.97,2.01 63.97,2.45 65.18,3.66 65.18,4.78 ; U3.2@61.58,7.04 62.92,7.04 65.18,4.78 ; 64.96,5.09 65.18,5.31 ; U3.6@67.168,5.77 65.64,5.77 65.18,5.31 ; 65.18,4.78 65.18,5.31
NetD8_A: D8.A R47.2 U4.2 U4.6 | length 13.4
  Top Layer w0.6: D8.A@30.58,2.41 30.98,2.01 32.97,2.01 32.97,2.45 34.18,3.66 34.18,4.78 ; U4.2@30.58,7.04 31.92,7.04 34.18,4.78 ; 33.96,5.09 34.18,5.31 ; U4.6@36.168,5.77 34.64,5.77 34.18,5.31 ; 34.18,4.78 34.18,5.31
NetJ1_3: J1.3 R9.2 R14.1 T3.2 | length 31.5
  Top Layer w0.35: T3.2@120.44,12.35 121.575,13.485 141.315,13.485 143.06,11.74 J1.3@143.06,8.5
  Top Layer w0.6: R14.1@142.48,4.41 142.63,4.56 R9.2@142.63,6.51 143.06,6.94 J1.3@143.06,8.5 ; T3.2@120.44,12.35 120.495,12.405 T3.2@120.44,12.35
NetJ1_5: J1.5 R10.1 R13.1 T2.2 | length 28.5
  Top Layer w0.35: T2.2@120.44,9.89 120.44,10.24 121.39,11.19 123.79,11.19 125.535,12.935 134.335,12.935 135.115,12.155 135.115,10.535 135.84,9.81 139.21,9.81 J1.5@140.52,8.5
  Top Layer w0.6: R10.1@140.29,4.58 140.36,4.51 R10.1@140.36,4.48 140.52,4.64 J1.5@140.52,8.5
NetJ2_3: J2.3 R24.2 R29.1 T8.2 | length 31.5
  Top Layer w0.35: T8.2@89.45,12.37 90.585,13.505 110.325,13.505 112.07,11.76 J2.3@112.07,8.52
  Top Layer w0.6: R29.1@111.49,4.43 111.64,4.58 111.64,6.53 112.07,6.96 J2.3@112.07,8.52 ; T8.2@89.45,12.37 89.505,12.425 T8.2@89.45,12.37
NetJ2_5: J2.5 R25.1 R28.1 T7.2 | length 28.5
  Top Layer w0.35: T7.2@89.45,9.91 89.45,10.26 90.4,11.21 92.8,11.21 94.545,12.955 103.345,12.955 104.125,12.175 104.125,10.555 104.85,9.83 108.22,9.83 J2.5@109.53,8.52
  Top Layer w0.6: R25.1@109.3,4.6 109.37,4.53 109.37,4.5 109.53,4.66 J2.5@109.53,8.52
NetJ3_3: J3.3 R39.2 R44.1 T13.2 | length 31.5
  Top Layer w0.35: T13.2@58.44,12.36 59.575,13.495 79.315,13.495 81.06,11.75 J3.3@81.06,8.51
  Top Layer w0.6: R44.1@80.48,4.42 80.63,4.57 R39.2@80.63,6.52 81.06,6.95 J3.3@81.06,8.51 ; T13.2@58.44,12.36 58.495,12.415 T13.2@58.44,12.36
NetJ3_5: J3.5 R40.1 R43.1 T12.2 | length 28.5
  Top Layer w0.35: T12.2@58.44,9.9 58.44,10.25 59.39,11.2 61.79,11.2 63.535,12.945 72.335,12.945 73.115,12.165 73.115,10.545 73.84,9.82 77.21,9.82 J3.5@78.52,8.51
  Top Layer w0.6: R40.1@78.29,4.59 78.36,4.52 78.36,4.49 78.52,4.65 J3.5@78.52,8.51
NetJ4_3: J4.3 R54.2 R59.1 T18.2 | length 31.5
  Top Layer w0.35: T18.2@27.44,12.36 28.575,13.495 41.035,13.495 41.98,12.55 49.26,12.55 50.06,11.75 J4.3@50.06,8.51
  Top Layer w0.6: R59.1@49.48,4.42 49.63,4.57 49.63,6.52 50.06,6.95 J4.3@50.06,8.51 ; T18.2@27.44,12.36 27.495,12.415 T18.2@27.44,12.36
NetJ4_5: J4.5 R55.1 R58.1 T17.2 | length 27.6
  Top Layer w0.35: T17.2@27.44,9.9 27.44,10.25 28.39,11.2 30.79,11.2 32.535,12.945 39.715,12.945 42.84,9.82 46.21,9.82 J4.5@47.52,8.51
  Top Layer w0.6: R55.1@47.29,4.59 47.36,4.52 47.36,4.49 47.52,4.65 J4.5@47.52,8.51
NetR3_2: R3.2 T2.1 | length 2.1
  Bottom Layer w0.6: T2.1@122.98,9.89 122.99,9.9 R3.2@125.09,9.9
NetR4_2: R4.2 T3.1 | length 2.1
  Bottom Layer w0.6: T3.1@122.98,12.35 122.99,12.34 R4.2@125.09,12.34
NetR18_2: R18.2 T7.1 | length 2.1
  Bottom Layer w0.6: T7.1@91.99,9.91 92,9.92 R18.2@94.1,9.92
NetR19_2: R19.2 T8.1 | length 2.1
  Bottom Layer w0.6: T8.1@91.99,12.37 92,12.36 R19.2@94.1,12.36
NetR33_2: R33.2 T12.1 | length 2.1
  Bottom Layer w0.6: T12.1@60.98,9.9 60.99,9.91 R33.2@63.09,9.91
NetR34_2: R34.2 T13.1 | length 2.1
  Bottom Layer w0.6: T13.1@60.98,12.36 T13.1@60.99,12.35 R34.2@63.09,12.35
NetR48_2: R48.2 T17.1 | length 2.1
  Bottom Layer w0.6: T17.1@29.98,9.9 29.99,9.91 R48.2@32.09,9.91
NetR49_2: R49.2 T18.1 | length 2.1
  Bottom Layer w0.6: T18.1@29.98,12.36 29.99,12.35 R49.2@32.09,12.35
NetR61_1: R61.1 U10.21 | length 4.5
  Top Layer w0.35: R61.1@27.38,94.48 27.38,92.8 28.43,91.75 U10.21@28.43,90.44
NetR62_2: R62.2 U11.21 | length 4.7
  Top Layer w0.35: R62.2@26.98,74.95 26.98,73.64 28.43,72.19 U11.21@28.43,70.9
NetR63_2: R63.2 U12.21 | length 5.1
  Top Layer w0.35: R63.2@27.25,55.565 26.81,55.125 26.81,54.26 28.43,52.64 U12.21@28.43,51.36
NetR64_1: R64.1 R65.1 U13.21 | length 7.6
  Top Layer w0.35: R65.1@26.4,36.025 26.44,35.985 26.98,35.985 26.98,34.6 28.43,33.15 U13.21@28.43,31.82 ; R65.1@26.42,36.025 R64.1@28.61,36.025
RS232-RX-1: U10.1 X5.1 | length 27.4
  Top Layer w0.35: v1(28.43,82.67) 30.06,82.67 30.5,82.23 34.82,82.23 36.11,80.94 U10.1@37.13,80.94
  Bottom Layer w0.35: X5.1@13.3,81.19 17.74,81.19 20.42,78.51 23.57,78.51 27.73,82.67 v1(28.43,82.67)
RS232-RX-2: U11.1 X7.1 | length 27.4
  Top Layer w0.35: v1(28.43,63.13) 30.06,63.13 30.5,62.69 34.82,62.69 36.11,61.4 U11.1@37.13,61.4
  Bottom Layer w0.35: X7.1@13.3,61.65 17.74,61.65 20.42,58.97 23.57,58.97 27.73,63.13 v1(28.43,63.13)
RS232-RX-3: U12.1 X9.1 | length 27.4
  Top Layer w0.35: v1(28.43,43.59) 30.06,43.59 30.5,43.15 34.82,43.15 36.11,41.86 U12.1@37.13,41.86
  Bottom Layer w0.35: X9.1@13.3,42.11 17.74,42.11 20.42,39.43 23.57,39.43 27.73,43.59 v1(28.43,43.59)
RS232-RX-4: U13.1 X11.1 | length 27.4
  Top Layer w0.35: v1(28.43,24.05) 30.06,24.05 30.5,23.61 34.82,23.61 36.11,22.32 U13.1@37.13,22.32
  Bottom Layer w0.35: X11.1@13.3,22.57 17.74,22.57 20.42,19.89 23.57,19.89 27.73,24.05 v1(28.43,24.05)
RS232-TX-1: U10.44 X6.1 | length 25.6
  Top Layer w0.35: v1(29.44,81.545) 34.545,81.545 35.63,80.46 U10.44@35.63,79.44
  Bottom Layer w0.35: X6.1@13.3,77.29 23.65,77.29 27.905,81.545 v1(29.44,81.545)
RS232-TX-2: U11.44 X8.1 | length 25.6
  Top Layer w0.35: v1(29.44,62.005) 34.545,62.005 35.63,60.92 U11.44@35.63,59.9
  Bottom Layer w0.35: X8.1@13.3,57.75 23.65,57.75 27.905,62.005 v1(29.44,62.005)
RS232-TX-3: U12.44 X10.1 | length 25.6
  Top Layer w0.35: v1(29.44,42.465) 34.545,42.465 35.63,41.38 U12.44@35.63,40.36
  Bottom Layer w0.35: X10.1@13.3,38.21 23.65,38.21 27.905,42.465 v1(29.44,42.465)
RS232-TX-4: U13.44 X12.1 | length 25.6
  Top Layer w0.35: v1(29.44,22.925) 34.545,22.925 35.63,21.84 U13.44@35.63,20.82
  Bottom Layer w0.35: X12.1@13.3,18.67 23.65,18.67 27.905,22.925 v1(29.44,22.925)
SCALING-1: R8.2 U10.11 | length 21.6
  Top Layer w0.35: 19.5,90.45 R8.2@18.61,90.45 v1@20.3,90.45 ; v1(37.03,90.4) 37.03,89.04 U10.11@37.13,88.94 ; v1@20.3,90.45 v1(20.35,90.4) v1@20.3,90.45
  Bottom Layer w0.35: v1(20.35,90.4) 24.5,90.4 25.33,89.57 36.2,89.57 v1(37.03,90.4)
SCALING-2: R23.2 U11.11 | length 21.5
  Top Layer w0.35: 19.5,70.91 18.61,70.91 v1@20.3,70.91 ; v1(37.03,70.86) 37.03,69.5 U11.11@37.13,69.4 ; v1@20.3,70.91 v1(20.35,70.86) v1@20.3,70.91
  Bottom Layer w0.35: v1(20.35,70.86) 24.47,70.86 25.15,70.18 36.35,70.18 v1(37.03,70.86)
SCALING-3: R38.2 U12.11 | length 21.5
  Top Layer w0.35: 19.5,51.37 R38.2@18.61,51.37 v1@20.3,51.37 ; v1(37.03,51.32) 37.03,49.96 U12.11@37.13,49.86 ; v1@20.3,51.37 v1(20.35,51.32) v1@20.3,51.37
  Bottom Layer w0.35: v1(20.35,51.32) 24.53,51.32 25.3,50.55 27.79,50.55 36.26,50.55 v1(37.03,51.32)
SCALING-4: R53.2 U13.11 | length 21.6
  Top Layer w0.35: 19.5,31.83 18.61,31.83 v1@20.3,31.83 ; v1(37.03,31.78) 37.03,30.42 U13.11@37.13,30.32 ; v1@20.3,31.83 v1(20.35,31.78) v1@20.3,31.83
  Bottom Layer w0.35: v1(20.35,31.78) 24.78,31.78 25.61,30.95 36.2,30.95 v1(37.03,31.78)
VCC_1,55V-1: C16.1 J1.1 J1.2 R3.1 R4.1 | length 29
  Top Layer w0.6: J1.2@144.33,11.04 144.33,11.02 145.6,9.75 J1.1@145.6,8.65 ; J1.1@145.6,8.5 145.63,8.53 C16.1@148.09,8.53
  Bottom Layer w0.6: R3.1@127.38,9.9 127.38,11.01 ; R4.1@127.38,12.34 127.38,11.01 ; J1.1@145.6,8.5 143.38,6.28 135.72,6.28 130.99,11.01 127.38,11.01
VCC_1,55V-2: C26.1 J2.1 J2.2 R18.1 R19.1 | length 29
  Top Layer w0.6: J2.2@113.34,11.06 113.34,11.04 114.61,9.77 J2.1@114.61,8.67 ; J2.1@114.61,8.52 114.64,8.55 C26.1@117.1,8.55
  Bottom Layer w0.6: R18.1@96.39,9.92 96.39,11.03 ; R19.1@96.39,12.36 96.39,11.03 ; J2.1@114.61,8.52 112.39,6.3 104.73,6.3 100,11.03 96.39,11.03
VCC_1,55V-3: C36.1 J3.1 J3.2 R33.1 R34.1 | length 29
  Top Layer w0.6: J3.2@82.33,11.05 82.33,11.03 83.6,9.76 J3.1@83.6,8.66 ; J3.1@83.6,8.51 83.63,8.54 C36.1@86.09,8.54
  Bottom Layer w0.6: R33.1@65.38,9.91 65.38,11.02 ; R34.1@65.38,12.35 65.38,11.02 ; J3.1@83.6,8.51 81.38,6.29 73.72,6.29 68.99,11.02 65.38,11.02
VCC_1,55V-4: C46.1 J4.1 J4.2 R48.1 R49.1 | length 29
  Top Layer w0.6: J4.2@51.33,11.05 51.33,11.03 52.6,9.76 J4.1@52.6,8.66 ; J4.1@52.6,8.51 52.63,8.54 C46.1@55.09,8.54
  Bottom Layer w0.6: R48.1@34.38,9.91 34.38,11.02 ; R49.1@34.38,12.35 34.38,11.02 ; J4.1@52.6,8.51 50.38,6.29 42.72,6.29 37.99,11.02 34.38,11.02
VCC_5V: C2.1 C3.1 C4.1 C5.1 C6.1 C7.1 C8.1 C9.1 C10.1 C11.1 C12.1 C15.1 C22.1 C25.1 C32.1 C35.1 C42.1 C45.1 Con1.2 Con2.2 Con3.2 Con4.2 D1.K R1.1 R2.1 R5.2 R7.1 R11.1 R12.2 R16.1 R17.1 R20.2 R22.1 R26.1 R27.2 R31.1 R32.1 R35.2 R37.1 R41.1 R42.2 R46.1 R47.1 R50.2 R52.1 R56.1 R57.2 R65.2 U1.8 U2.8 U3.8 U4.8 U5.19 U6.19 U8.19 U9.19 U10.7 U10.28 U11.7 U11.28 U12.7 U12.28 U13.7 U13.28 | length 709.9
  Top Layer w0.35: v1(22.31,29.78) 23.96,28.13 23.96,26.95 24.59,26.32 U13.28@26.13,26.32 ; v1(22.31,49.32) 23.96,47.67 23.96,46.49 24.59,45.86 U12.28@26.13,45.86 ; v1(22.31,68.86) 23.96,67.21 23.96,66.03 24.59,65.4 U11.28@26.13,65.4 ; v1(22.31,88.4) 23.96,86.75 23.96,85.57 24.59,84.94 U10.28@26.13,84.94
  Top Layer w0.4: U13.28@26.13,26.32 29.79,26.32 30.44,25.67 34.08,25.67 35.53,27.12 U13.7@37.13,27.12 39.58,27.12 C45.1@40.3,27.84 ; U12.28@26.13,45.86 29.79,45.86 30.44,45.21 34.08,45.21 35.53,46.66 U12.7@37.13,46.66 39.58,46.66 C35.1@40.3,47.38 ; U11.28@26.13,65.4 29.79,65.4 30.44,64.75 34.08,64.75 35.53,66.2 U11.7@37.13,66.2 39.58,66.2 C25.1@40.3,66.92 ; U10.28@26.13,84.94 29.79,84.94 30.44,84.29 34.08,84.29 35.53,85.74 U10.7@37.13,85.74 39.58,85.74 C15.1@40.3,86.46
  Top Layer w0.6: R47.1@35.26,2.01 37.19,2.01 38.05,2.87 v1(38.05,3.68) ; U4.8@36.168,8.31 36.22,8.362 36.22,9.63 ; C42.1@36.22,10.54 36.22,9.63 ; v1(36.83,9.28) 36.57,9.28 36.22,9.63 ; R32.1@66.26,2.01 68.19,2.01 69.05,2.87 v1(69.05,3.68) ; U3.8@67.168,8.31 67.22,8.362 67.22,9.63 ; C32.1@67.22,10.55 67.22,9.63 ; v1(67.83,9.28) 67.57,9.28 67.22,9.63 ; R17.1@97.27,2.02 99.2,2.02 100.06,2.88 v1(100.06,3.69) ; U2.8@98.178,8.32 98.23,8.372 98.23,9.64 ; C22.1@98.23,10.55 98.23,9.64 ; v1(98.84,9.29) 98.58,9.29 98.23,9.64 ; R2.1@128.26,2 130.19,2 131.05,2.86 v1(131.05,3.67) ; U1.8@129.168,8.3 129.22,8.352 129.22,9.62 ; C12.1@129.22,10.54 129.22,9.62 ; v1(129.83,9.27) 129.57,9.27 129.22,9.62
  Top Layer w1: Con4.2@2.3,19.92 3.61,19.92 v1(7.57,23.88) ; Con3.2@2.3,39.46 3.61,39.46 v1(7.57,43.42) 8.11,42.88 v1(8.11,29.63) ; Con2.2@2.3,59 3.61,59 v1(7.57,62.96) 7.929,62.601 v1(7.929,48.841) ; Con1.2@2.3,78.54 3.61,78.54 v1(7.57,82.5) 7.97,82.1 v1(7.97,68.4) ; v1(23.91,14.25) 23.974,14.186 23.974,14.09 24.865,14.98 v1(36.77,14.98) 41.83,14.98 43.23,13.58 ; R65.2@24.09,36.025 R65.2@24.11,36.005 ; R65.2@24.13,36.025 R65.2@24.11,36.005 ; v1(25.69,33.37) 24.135,34.925 24.135,35.98 R65.2@24.11,36.005 ; 43.24,13.58 48.62,13.58 ; 48.6,13.58 48.62,13.58 ; U9.19@48.67,33.94 C8.1@48.67,30.94 51.22,28.39 C9.1@51.22,27.86 ; U8.19@48.67,53.48 C11.1@48.67,50.48 51.22,47.93 C10.1@51.22,47.4 ; U6.19@48.67,73.02 48.67,70.02 51.22,67.47 C5.1@51.22,66.94 ; U5.19@48.67,92.56 C7.1@48.67,89.56 51.22,87.01 C6.1@51.22,86.48 ; 55.3,14.98 51.4,14.98 50,13.58 48.62,13.58 ; 55.31,14.98 v1(56.36,14.98) 87.78,14.98 ; v1(87.78,13.14) 87.78,14.98 ; v1(118.26,12.75) 116.03,14.98 87.78,14.98
  Bottom Layer w0.35: v1@22.29,29.76 v1(22.31,29.78) ; v1@22.29,49.3 v1(22.31,49.32) ; v1@22.29,68.84 v1(22.31,68.86) ; v1@22.29,88.38 v1(22.31,88.4)
  Bottom Layer w0.6: 9.11,26.82 15.5,26.82 15.54,26.82 ; 9.11,46.36 15.5,46.36 15.54,46.36 ; 9.11,65.9 15.5,65.9 ; 9.11,85.44 15.5,85.44 ; 15.476,65.876 15.5,65.9 ; 15.476,85.416 15.5,85.44 ; R26.1@18.61,72.9 25.6,72.9 26.86,71.64 32.96,71.64 33.67,72.35 33.67,73.8 34.79,74.92 44.35,74.92 46.68,74.92 48.58,73.02 U6.19@48.67,73.02 ; R56.1@18.64,33.78 18.93,34.07 25.73,34.07 27.37,32.43 33.08,32.43 33.65,33 33.65,34.87 34.44,35.66 46.95,35.66 U9.19@48.67,33.94 ; R11.1@18.64,92.25 18.87,92.48 25.67,92.48 27.02,91.13 30.39,91.13 32.67,91.13 33.62,92.08 33.62,92.99 35,94.37 46.71,94.37 U5.19@48.54,92.54 ; v1@23.9,14.25 23.9,9.44 24.76,8.58 24.76,5.9 27.67,2.99 29.53,2.99 32.05,5.51 36.22,5.51 ; 32.63,52.05 33.613,53.033 33.613,54.073 34.64,55.1 ; v1(36.77,14.98) 37.28,15.49 R50.2@38.51,15.49 ; v1(36.83,9.28) 36.83,6.84 36.22,6.23 36.22,5.51 ; v1(38.05,3.68) 36.22,5.51 ; v1(56.36,14.98) 56.39,14.95 56.39,11.21 57.15,10.45 57.15,8.14 58.54,6.75 58.54,3.51 59.06,2.99 60.53,2.99 63.05,5.51 67.22,5.51 ; v1(67.83,9.28) 67.83,6.84 67.22,6.23 67.22,5.51 ; v1(69.05,3.68) 67.22,5.51 ; v1(87.78,13.14) 87.78,8.53 89.55,6.76 89.55,3.52 90.07,3 91.54,3 94.06,5.52 98.23,5.52 ; v1(98.84,9.29) 98.84,6.85 98.23,6.24 98.23,5.52 ; v1(100.06,3.69) 98.23,5.52 ; v1(118.26,12.75) 118.26,12.29 118.78,11.77 118.78,8.5 120.54,6.74 120.54,3.5 121.06,2.98 122.53,2.98 125.05,5.5 129.22,5.5 ; v1(129.83,9.27) 129.83,6.83 129.22,6.22 129.22,5.5 ; v1(131.05,3.67) 129.22,5.5 ; 15.5,65.9 15.54,65.9 15.5,65.9 ; 15.5,85.44 15.54,85.44 15.5,85.44
  Bottom Layer w1: 7.57,16.96 v1(7.57,23.88) 7.57,25.86 8.53,26.82 ; v1(7.57,43.42) 7.57,45.4 8.53,46.36 ; v1(7.57,62.96) 7.57,64.94 8.53,65.9 ; v1(7.57,82.5) 7.57,84.48 8.53,85.44 9.11,85.44 ; D1.K@7.67,16.06 8.02,15.71 C3.1@9.44,15.71 ; v1@7.84,48.93 v1(7.929,48.841) 8.53,48.24 8.53,46.36 ; v1(7.97,68.4) 7.97,68.39 8.53,67.83 8.53,65.9 ; v1(8.11,29.63) 8.53,29.21 8.53,26.82 ; 9.11,26.82 8.53,26.82 ; 9.11,46.36 8.53,46.36 ; 9.11,65.9 8.53,65.9 ; 15.54,26.82 17.73,26.82 18.64,27.73 R46.1@18.64,29.76 ; 15.54,46.36 17.73,46.36 18.64,47.27 R31.1@18.64,49.3 ; 15.54,65.9 17.73,65.9 18.64,66.81 R16.1@18.64,68.84 ; 15.54,85.44 17.73,85.44 18.64,86.35 R1.1@18.64,88.38 ; R41.1@18.61,53.36 18.77,53.52 25.42,53.52 26.89,52.05 32.63,52.05 ; R56.1@18.64,33.78 R52.1@18.64,31.76 R46.1@18.64,29.76 ; R41.1@18.64,53.32 R37.1@18.64,51.3 R31.1@18.64,49.3 ; R26.1@18.64,72.86 R22.1@18.64,70.84 R16.1@18.64,68.84 ; R11.1@18.64,92.4 18.64,92.25 R7.1@18.64,90.38 R1.1@18.64,88.38 ; v1@22.29,29.76 R46.1@18.64,29.76 ; R57.2@22.68,14.25 v1@23.9,14.25 ; R42.2@25.25,46.31 R35.2@25.25,48.32 25.19,48.38 23.21,48.38 22.29,49.3 R31.1@18.64,49.3 ; R27.2@25.25,65.85 R20.2@25.25,67.86 25.19,67.92 23.21,67.92 22.29,68.84 R16.1@18.64,68.84 ; R12.2@25.25,85.39 R5.2@25.25,87.4 25.19,87.46 23.21,87.46 22.29,88.38 R1.1@18.64,88.38 ; 34.64,55.1 47.05,55.1 U8.19@48.67,53.48
  Bottom Layer w2: D1.K@7.67,16.06 7.67,14.79 10.51,11.95 C2.1@14.33,11.95 15.98,11.95 18.23,14.2 v1@23.68,14.2
pads on no net: Con1.6 Con2.6 Con3.6 Con4.6 H1.1 H2.1 H3.1 H4.1 J1.MH1 J1.MH2 J1.MH3 J1.MH4 J2.MH1 J2.MH2 J2.MH3 J2.MH4 J3.MH1 J3.MH2 J3.MH3 J3.MH4 J4.MH1 J4.MH2 J4.MH3 J4.MH4 U5.18 U5.21 U6.18 U6.21 U8.18 U8.21 U9.18 U9.21 U10.12 U10.13 U10.14 U10.22 U10.23 U10.24 U10.25 U10.26 U10.27 U10.32 U10.33 U10.34 U10.35 U10.36 U10.37 U10.42 U10.43 U11.12 U11.13 U11.14 U11.22 U11.23 U11.24 U11.25 U11.26 U11.27 U11.32 U11.33 U11.34 U11.35 U11.36 U11.37 U11.42 U11.43 U12.12 U12.13 U12.14 U12.22 U12.23 U12.24 U12.25 U12.26 U12.27 U12.32 U12.33 U12.34 U12.35 U12.36 U12.37 U12.42 U12.43 U13.12 U13.13 U13.14 U13.22 U13.23 U13.24 U13.25 U13.26 U13.27 U13.32 U13.33 U13.34 U13.35 U13.36 U13.37 U13.42 U13.43

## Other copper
Top Layer:
  text "4Fach-Anz-Dreh" at 53.1,96.18 h2
  text "Rev 1.1" at 84.92,95.83 h2
  text "by MK" at 103.6,95.83 h2
  text "19.08.2010" at 120.9,95.66 h2
  text "2" at 182.978,-54.47 h1.27
  text "Top Layer" at 195.558,-54.57 h1.27
Bottom Layer:
  text "VCC-5V" at 19.26,4.83 h1
  text "+" at 13.877,1.78 h1.5
  text "-" at 18.07,1.6 h1.5
  text "3" at 182.978,-54.47 h1.27
  text "Bottom Layer" at 195.558,-54.57 h1.27

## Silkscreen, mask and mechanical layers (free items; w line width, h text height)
Top Overlay:
  text "1" at 183.148,-54.46 h1.27
  text "Top Overlay" at 195.558,-54.57 h1.27
Bottom Overlay:
  text "4" at 182.978,-54.47 h1.27
  text "Bottom Overlay" at 195.558,-54.57 h1.27
Mechanical 1:
  the board outline again, w0.2
Mechanical 16:
  lines w0.127: -62.02,-12.19 -56.94,-12.19 ; -62.02,36.07 -56.94,36.07 ; -62.02,84.33 -56.94,84.33 ; 7.98,-60.45 7.98,-55.37 ; 7.98,127.51 7.98,132.59 ; 77.98,-60.45 77.98,-55.37 ; 77.98,127.51 77.98,132.59 ; 147.98,-60.45 147.98,-55.37 ; 147.98,127.51 147.98,132.59 ; 212.9,-12.19 217.98,-12.19 ; 212.9,36.07 217.98,36.07 ; 212.9,84.33 217.98,84.33 ; -62.02,-60.45 217.98,-60.45 217.98,132.59 -62.02,132.59 -62.02,-60.45 ; -56.94,-55.37 -56.94,127.51 212.9,127.51 212.9,-55.37 -56.94,-55.37
  lines w0.2: 50.067,-55.171 50.067,-35.359 117.821,-35.382 ; 117.839,-55.37 117.839,-35.37 212.839,-35.37 ; 117.839,-52.37 194.839,-52.37 212.839,-52.37 ; 117.839,-49.37 174.839,-49.37 ; 117.839,-44.37 174.839,-44.37 ; 127.839,-49.37 127.839,-44.37 ; 159.795,-52.37 159.795,-44.37 ; 174.839,-55.37 174.839,-35.37 ; 194.839,-55.37 194.839,-35.37
  text "1" at -25.774,129.161 h1.78
  text "2" at 46.87,129.161 h1.78
  text "3" at 120.022,129.161 h1.78
  text "4" at 192.92,129.161 h1.78
  text "A" at -60.115,106.149 h1.78
  text "A" at 214.805,106.149 h1.78
  text "B" at -60.115,58.092 h1.78
  text "B" at 214.805,58.092 h1.78
  text "C" at -60.115,9.578 h1.78
  text "C" at 214.805,9.578 h1.78
  text "D" at -60.115,-38.428 h1.78
  text "D" at 214.805,-38.428 h1.78
  text "Copying of this document, and giving it to others and the use or comunication of the" at 51.261,-38.686 h1
  text "4Fach-Anzeige-Drehbank" at 120.428,-40.55 h2.27
  text "contents therof, ar forbidden without express authority. Offenders are liable to the" at 51.261,-40.718 h1
  text "payment of damages. All rights are reserved in the event of the grant of a patent or" at 51.261,-42.75 h1
  text "the registration of a utility model or design." at 51.261,-44.782 h1
  text "by MK" at 196.98,-45.66 h3
  text "Weitergabe sowie vervielfaeltigung dieser Unterlage, Verwertung und Mitteilung ihres Inhalts" at 51.261,-47.322 h1
  text "Size:" at 118.539,-47.57 h1.27
  text "A4" at 123.839,-47.57 h1.27
  text "Number:" at 128.639,-47.57 h1.27
  text "Revision: 1.1" at 160.929,-47.57 h1.27
  text "1.0" at 139.74,-47.72 h1.27
  text "nicht gestattet, soweit nicht ausdruecklich zugestanden. Zuwiederhandlung verpflichtet zu" at 51.261,-49.354 h1
  text "Schadensersatz. Alle Rechte fuer den Fall der Patenterteilung oder Gebrauchsmuster-" at 51.261,-51.386 h1
  text ".Pcb_File_Name_No_Path" at 118.539,-51.47 h1.27
  text "Project: P_030" at 160.929,-51.634 h1.27
  text "Eintragungen vorbehalten." at 51.261,-53.418 h1
  text "Print Date:" at 143.44,-54.4 h1.27
  text "Date:" at 118.539,-54.47 h1.27
  text "20.10.2010" at 124.339,-54.47 h1.27
  text ".Print_Date" at 155.059,-54.47 h1.27
  text "Sheet    of 4" at 176.339,-54.47 h1.27
  text "1" at -25.774,-58.799 h1.78
  text "2" at 46.87,-58.799 h1.78
  text "3" at 120.022,-58.799 h1.78
  text "4" at 192.92,-58.799 h1.78

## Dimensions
160,0 to 149.095,-7.92 on Mechanical 15
133.215,-7.92 to 149.095,-7.92 on Mechanical 15
0,0 to 133.215,-7.92 on Mechanical 15
0,0 to 102.215,-7.92 on Mechanical 15
0,0 to 71.215,-7.92 on Mechanical 15
0,0 to 40.215,-7.92 on Mechanical 15
160,0 to 150.56,93.84 on Mechanical 15
160,0 to 150.56,17.38 on Mechanical 15
0,100 to 150.56,93.84 on Mechanical 15
0,100 to 73,93.84 on Mechanical 15
5,95 to 155,95 on Mechanical 15
5,5 to 5,95 on Mechanical 15
0,100 to 0,0 on Mechanical 15
0,0 to 160,0 on Mechanical 15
